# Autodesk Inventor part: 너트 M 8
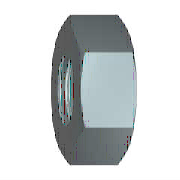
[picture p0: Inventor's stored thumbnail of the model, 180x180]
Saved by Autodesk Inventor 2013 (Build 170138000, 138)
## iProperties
IsCustomPart: 1
Created: 2012-02
Part Number: 너트 M 8
Material: 강철, 연강
Description: 6각 너트 및 6각 가는 너트
Document SubType Name: Modeling
Standard: KS B 1012
Designer: mduedu
Standards Organization: KS
Language: ko-KR
Size Designation: M 8
Categories: <MemberInstance><Categories><Category DisplayName="조임쇠" InternalName="e4da775c-781d-43d5-af7c-5136215cf5a6" Mnemonic="FSTN"><Category DisplayName="너트" InternalN
Density: 7.86 g/cm^3
Mass: 4.30432 g
Surface Area: 5.27675 cm^2
Volume: 0.547623 cm^3
Author: mduedu
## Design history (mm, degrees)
sketch "스케치1"
  geometry: L1 (-7.506, 0)-(-3.753, 6.5); L2 (-3.753, 6.5)-(3.753, 6.5); L3 (3.753, 6.5)-(7.506, 0); L4 (7.506, 0)-(3.753, -6.5); L5 (3.753, -6.5)-(-3.753, -6.5); L6 (-3.753, -6.5)-(-7.506, 0); 2 further points
  constraints: 12 end point, 1 coincident, 1 horizontal, 11 other
  dimensions: "d0" = 15.01111 distance of L3.end L1.start (= 1.1547 x SW)
extrude "본체" new body sketch "스케치1" distance "d1" = 5 (= KOH); taper "d2" = 0 deg
sketch "스케치2"
  geometry: L1 (0, 3.753)-(0, 7.506) reference; L2 (0, 7.506)-(5, 7.506) reference; L3 (5, 3.753)-(5, 7.506) reference; L4 (-1, 0)-(6, 0) reference; L5 (0.581, 7.506)-(0, 6.5); L6 (4.419, 7.506)-(5, 6.5)
  constraints: 4 end point, 4 point on line
  dimensions: "d3" = 30 deg angle of L1 L5 (= ANG1); "d4" = 30 deg angle of L3 L6 (= ANG2); "d5" = 13 diameter of L5.end L4 (= SW0); "d6" = 13 diameter of L6.end L4 (= SW01)
revolve "모따기1" sketch "스케치2" stored, may be unused: angle "d7" = 90 deg
sketch "스케치3"
  geometry: A1 r 6.5 centre (0, 0) between (-3.25, -5.629) and (3.25, -5.629) reference; 1 further point
  constraints: 1 coincident
hole "스레드" sketch "스케치3" at (0, 0) diameter "d25" = 6.647; stored, may be unused: countersink angle "d29" = 82 deg, drill point angle "d31" = 118 deg; dims "d26" = 6, "d27" = 4, "d28" = 2, "d30" = 8
workaxis "Work Axis1"
workplane "Work Plane1"
body "Solid1"
chamfer "모따기2" distance "d8" = 0.67658 (= -0.5 x GD1 + 0.5 x NND); stored, may be unused: angle "d9" = 30 deg, second distance "d40" = 0.67658 (= -0.5 x GD1 + 0.5 x NND)
chamfer "모따기3" distance "d10" = 0.67658 (= -0.5 x GD1 + 0.5 x NND); stored, may be unused: angle "d11" = 30 deg, second distance "d41" = 0.67658 (= -0.5 x GD1 + 0.5 x NND)
other parameters: "ANG1" = 30 deg [user parameter; used in 1 equation term], "ANG2" = 30 deg [user parameter; used in 1 equation term], "NND" = 8 [user parameter; used in 4 equation terms], "KOH" = 5 [user parameter; used in 1 equation term], "SW" = 13 [user parameter; used in 4 equation terms], "SW0" = 13 (= SW) [user parameter; used in 1 equation term], "SW01" = 13 (= SW) [user parameter; used in 1 equation term], "GD1" = 6.64684 (computed from THREADDIA, PTC, TOA) [user parameter; used in 4 equation terms], "d13" = 0, "d14" = 0, "d39" = 0, "d42" = 0, "GUL" = 0.67658 (= 0.541266 x PTC) [user parameter], "TPU" = 8 (computed from PTC) [user parameter], "THREADDIA" = 8 [user parameter; used in 1 equation term], "TOA" = 30 deg [user parameter; used in 1 equation term], "PTC" = 1.25 [user parameter; used in 4 equation terms], "E0" = 15.015 (= 1.155 x SW) [user parameter], "GAL" = 0.67658 (= 0.541266 x PTC) [user parameter]
